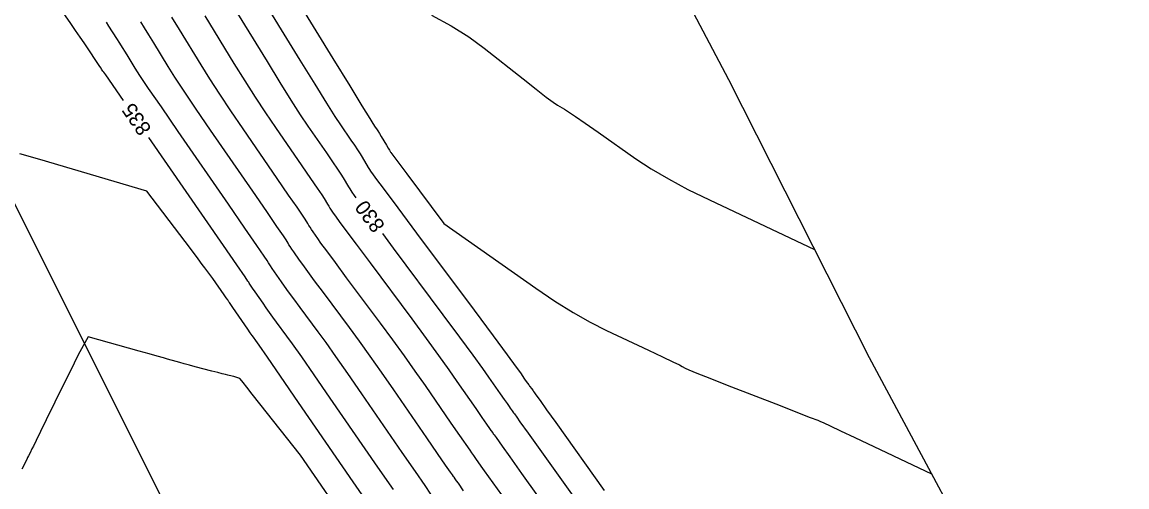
# Model space of a CAD drawing. Extents: x 1715724 to 1716561, y 394063 to 395906.
# Drawn here: x 1716345.4 to 1716449.4, y 394468.5 to 394512.3 of the extents above; entities that cross this region are included whole.
import ezdxf

# ---------------------------------------------------------------- set-up
doc = ezdxf.new("R2010")
doc.units = 0
for name, color, linetype in [('DT_X_Contour_Major', 7, 'Continuous'), ('DT_X_Contour_Minor', 7, 'Continuous'), ('DT_X_TIN_Hull', 7, 'Continuous'), ('GE_P_CL_10', 7, 'Continuous')]:
    doc.layers.add(name, color=color, linetype=linetype)

msp = doc.modelspace()

# ---------------------------------------------------------------- linework, layer by layer
at = {"layer": 'DT_X_Contour_Major'}
for points in [[(1716354.92, 394504.91), (1716353.24, 394507.35), (1716353.05, 394507.6), (1716353.01, 394507.66), (1716352.98, 394507.7), (1716352.92, 394507.79), (1716352.85, 394507.88), (1716352.8, 394507.97), (1716352.68, 394508.14), (1716352.5, 394508.41), (1716351.52, 394509.88), (1716351.21, 394510.34), (1716350.84, 394510.89), (1716350.4, 394511.53), (1716349.89, 394512.26), (1716347.37, 394515.88)], [(1716365, 394514.17), (1716368.43, 394508.58), (1716369.63, 394506.62), (1716370.68, 394504.96), (1716371.56, 394503.58), (1716372.29, 394502.5), (1716374.02, 394499.99), (1716374.6, 394499.14), (1716375.06, 394498.47), (1716375.39, 394497.97), (1716375.6, 394497.64), (1716376.11, 394496.8), (1716376.23, 394496.61), (1716376.33, 394496.44), (1716376.42, 394496.3), (1716376.65, 394495.97), (1716376.8, 394495.77)], [(1716380.33, 394468.27), (1716378.86, 394470.4), (1716374.39, 394476.89), (1716372.88, 394479.08), (1716371.7, 394480.78), (1716370.84, 394482), (1716370.31, 394482.73), (1716369.34, 394484.03), (1716368.99, 394484.51), (1716368.66, 394484.97), (1716368.35, 394485.4), (1716368.06, 394485.82), (1716367.32, 394486.9), (1716367.07, 394487.26), (1716366.88, 394487.53), (1716366.76, 394487.71), (1716366.71, 394487.8), (1716366.64, 394487.91), (1716366.36, 394488.31), (1716365.6, 394489.43), (1716364.34, 394491.26), (1716362.58, 394493.8), (1716357.31, 394501.45)], [(1716379.3, 394492.4), (1716380.32, 394491.02), (1716384.99, 394484.75), (1716386.57, 394482.62), (1716387.82, 394480.93), (1716388.73, 394479.68), (1716389.3, 394478.87), (1716390.39, 394477.3), (1716390.75, 394476.77), (1716391.03, 394476.37), (1716391.23, 394476.09), (1716391.34, 394475.94), (1716391.52, 394475.69), (1716391.59, 394475.6), (1716391.65, 394475.51), (1716391.72, 394475.42), (1716391.95, 394475.09), (1716392.25, 394474.66), (1716393.02, 394473.58), (1716394.27, 394471.83), (1716395.99, 394469.42), (1716402.94, 394459.7)]]:
    msp.add_lwpolyline(points, dxfattribs=at)
at = {"layer": 'DT_X_Contour_Minor'}
for points in [[(1716369.83, 394516.73), (1716374.63, 394508.88), (1716376.22, 394506.29), (1716377.37, 394504.41), (1716378.1, 394503.22), (1716378.4, 394502.75), (1716378.63, 394502.41), (1716378.73, 394502.26), (1716378.86, 394502.07), (1716379.01, 394501.82), (1716379.18, 394501.54), (1716379.68, 394500.71), (1716379.84, 394500.44), (1716379.96, 394500.24), (1716380.04, 394500.11), (1716380.07, 394500.07), (1716380.09, 394500.03), (1716380.19, 394499.9), (1716380.47, 394499.52), (1716380.94, 394498.89), (1716381.6, 394498.01), (1716385.08, 394493.33), (1716393.73, 394487.26), (1716395.53, 394486.03), (1716397.25, 394484.96), (1716398.87, 394484.04), (1716400.4, 394483.26), (1716404.36, 394481.4), (1716405.67, 394480.78), (1716406.63, 394480.32), (1716407.26, 394480.02), (1716407.53, 394479.88), (1716407.81, 394479.71), (1716408.14, 394479.56), (1716408.91, 394479.25), (1716410.12, 394478.77), (1716411.77, 394478.12), (1716416.75, 394476.18), (1716418.39, 394475.54), (1716419.58, 394475.08), (1716420.3, 394474.8), (1716420.56, 394474.7), (1716420.64, 394474.67), (1716420.86, 394474.56), (1716421.46, 394474.28), (1716422.44, 394473.82), (1716423.79, 394473.18), (1716431.01, 394469.76)], [(1716367.42, 394515.45), (1716371.53, 394508.73), (1716372.92, 394506.46), (1716374.02, 394504.68), (1716374.83, 394503.4), (1716375.35, 394502.62), (1716376.33, 394501.2), (1716376.67, 394500.7), (1716376.96, 394500.27), (1716377.2, 394499.9), (1716377.39, 394499.59), (1716377.97, 394498.62), (1716378.09, 394498.42), (1716378.18, 394498.28), (1716378.25, 394498.18), (1716378.37, 394498), (1716378.66, 394497.6), (1716379.45, 394496.54), (1716380.74, 394494.81), (1716382.52, 394492.42), (1716387.93, 394485.16), (1716389.72, 394482.75), (1716391.04, 394480.96), (1716391.9, 394479.8), (1716392.29, 394479.27), (1716392.69, 394478.68), (1716392.84, 394478.47), (1716392.96, 394478.29), (1716393.07, 394478.15), (1716393.15, 394478.03), (1716393.36, 394477.75), (1716393.43, 394477.66), (1716393.49, 394477.58), (1716393.53, 394477.52), (1716393.62, 394477.39), (1716393.76, 394477.19), (1716394.14, 394476.66), (1716394.76, 394475.79), (1716395.62, 394474.59), (1716400.19, 394468.2)], [(1716390.53, 394467.77), (1716388.91, 394470.03), (1716388.61, 394470.47), (1716388.1, 394471.21), (1716387.9, 394471.48), (1716387.71, 394471.75), (1716387.55, 394471.98), (1716386.58, 394473.37), (1716385.78, 394474.54), (1716383.34, 394478.08), (1716382.39, 394479.44), (1716381.37, 394480.87), (1716380.28, 394482.37), (1716379.12, 394483.94), (1716375.93, 394488.23), (1716374.87, 394489.66), (1716374.06, 394490.75), (1716373.51, 394491.5), (1716373.21, 394491.91), (1716372.78, 394492.54), (1716372.63, 394492.77), (1716372.49, 394492.98), (1716372.37, 394493.16), (1716372.27, 394493.33), (1716372.01, 394493.75), (1716371.78, 394494.11), (1716371.27, 394494.86), (1716370.47, 394496.02), (1716369.4, 394497.57), (1716366.18, 394502.25), (1716365.02, 394503.94), (1716363.98, 394505.51), (1716363.05, 394506.95), (1716362.22, 394508.27), (1716360.18, 394511.62), (1716359.48, 394512.76)], [(1716362.59, 394512.89), (1716365.32, 394508.42), (1716366.34, 394506.79), (1716367.33, 394505.24), (1716368.29, 394503.76), (1716369.23, 394502.38), (1716371.71, 394498.78), (1716372.54, 394497.58), (1716373.16, 394496.66), (1716373.59, 394496.04), (1716373.8, 394495.7), (1716374.12, 394495.17), (1716374.24, 394494.98), (1716374.36, 394494.79), (1716374.48, 394494.6), (1716374.6, 394494.42), (1716374.93, 394493.94), (1716375.23, 394493.54), (1716375.86, 394492.68), (1716376.82, 394491.38), (1716378.13, 394489.62), (1716382.06, 394484.35), (1716383.43, 394482.5), (1716384.59, 394480.9), (1716385.56, 394479.56), (1716386.32, 394478.47), (1716388.08, 394475.92), (1716388.67, 394475.07), (1716389.1, 394474.44), (1716389.39, 394474.03), (1716389.52, 394473.84), (1716389.68, 394473.63), (1716389.74, 394473.54), (1716389.82, 394473.44), (1716389.91, 394473.31), (1716390, 394473.17), (1716390.28, 394472.78), (1716390.58, 394472.35), (1716391.29, 394471.36), (1716392.4, 394469.8), (1716393.91, 394467.68)], [(1716383.93, 394512.96), (1716385.77, 394511.96), (1716387.42, 394510.92), (1716388.88, 394509.85), (1716392.54, 394506.95), (1716393.77, 394505.99), (1716394.71, 394505.25), (1716395.38, 394504.75), (1716395.77, 394504.49), (1716396.43, 394504.1), (1716396.82, 394503.86), (1716397.48, 394503.42), (1716398.4, 394502.78), (1716399.61, 394501.94), (1716403.17, 394499.44), (1716404.6, 394498.49), (1716406.24, 394497.53), (1716408.06, 394496.55), (1716410.09, 394495.56), (1716419.99, 394490.89)], [(1716383.87, 394467.86), (1716383.31, 394468.66), (1716382.41, 394469.97), (1716381.16, 394471.78), (1716377.37, 394477.28), (1716376.05, 394479.2), (1716374.92, 394480.81), (1716373.99, 394482.12), (1716373.25, 394483.13), (1716371.54, 394485.43), (1716370.95, 394486.23), (1716370.46, 394486.9), (1716370.07, 394487.44), (1716369.78, 394487.85), (1716369.14, 394488.78), (1716368.92, 394489.1), (1716368.75, 394489.34), (1716368.63, 394489.53), (1716368.56, 394489.64), (1716368.43, 394489.86), (1716368.17, 394490.25), (1716367.47, 394491.26), (1716366.34, 394492.9), (1716364.79, 394495.16), (1716360.06, 394502.01), (1716358.48, 394504.31), (1716357.28, 394506.06), (1716356.46, 394507.29), (1716356.02, 394507.97), (1716355.35, 394509.06), (1716355.09, 394509.48), (1716354.83, 394509.9), (1716354.56, 394510.33), (1716354.29, 394510.76), (1716353.55, 394511.93), (1716353.31, 394512.31)], [(1716386.93, 394468.16), (1716386.45, 394468.87), (1716386.28, 394469.11), (1716386.16, 394469.29), (1716386.06, 394469.43), (1716386, 394469.51), (1716385.89, 394469.66), (1716385.71, 394469.92), (1716385.24, 394470.59), (1716384.5, 394471.67), (1716383.47, 394473.16), (1716380.36, 394477.68), (1716379.22, 394479.32), (1716378.15, 394480.84), (1716377.13, 394482.25), (1716376.19, 394483.54), (1716373.74, 394486.83), (1716372.91, 394487.94), (1716372.26, 394488.82), (1716371.79, 394489.47), (1716371.5, 394489.88), (1716370.96, 394490.66), (1716370.77, 394490.93), (1716370.62, 394491.16), (1716370.5, 394491.34), (1716370.41, 394491.48), (1716370.22, 394491.8), (1716369.97, 394492.18), (1716369.37, 394493.06), (1716368.41, 394494.46), (1716367.1, 394496.37), (1716363.12, 394502.13), (1716361.75, 394504.12), (1716360.63, 394505.79), (1716359.75, 394507.12), (1716359.12, 394508.12), (1716357.76, 394510.34), (1716357.29, 394511.12), (1716356.88, 394511.78), (1716356.54, 394512.33)], [(1716378.24, 394466.57), (1716376.55, 394469.02), (1716371.41, 394476.49), (1716369.71, 394478.95), (1716368.47, 394480.75), (1716367.7, 394481.87), (1716367.38, 394482.32), (1716367.15, 394482.63), (1716367.03, 394482.79), (1716366.86, 394483.04), (1716366.63, 394483.37), (1716366.34, 394483.79), (1716365.49, 394485.02), (1716365.22, 394485.42), (1716365.02, 394485.71), (1716364.9, 394485.89), (1716364.85, 394485.95), (1716364.85, 394485.96), (1716364.73, 394486.14), (1716364.58, 394486.34), (1716364.39, 394486.63), (1716363.32, 394488.17), (1716362.58, 394489.17), (1716362.34, 394489.49), (1716361.95, 394490), (1716361.41, 394490.72), (1716360.72, 394491.63), (1716357.12, 394496.37), (1716347.05, 394499.35), (1716345.15, 394499.91)], [(1716376.5, 394464.37), (1716371.57, 394471.53), (1716367.76, 394476.35), (1716367.04, 394477.26), (1716366.52, 394477.93), (1716366.19, 394478.35), (1716366.05, 394478.52), (1716365.86, 394478.75), (1716365.58, 394478.84), (1716365.51, 394478.87), (1716365.41, 394478.89), (1716365.3, 394478.92), (1716365.15, 394478.96), (1716364.74, 394479.05), (1716364.53, 394479.1), (1716364.21, 394479.19), (1716363.79, 394479.3), (1716363.25, 394479.44), (1716361.68, 394479.85), (1716361.13, 394480), (1716360.64, 394480.13), (1716360.23, 394480.24), (1716359.89, 394480.33), (1716359.07, 394480.56), (1716358.67, 394480.67), (1716358.09, 394480.83), (1716357.33, 394481.05), (1716356.39, 394481.31), (1716351.59, 394482.65), (1716350.82, 394481.25), (1716350.6, 394480.83), (1716350.27, 394480.17), (1716349.82, 394479.28), (1716349.27, 394478.16), (1716347.65, 394474.84), (1716347.11, 394473.74), (1716346.7, 394472.91), (1716346.43, 394472.37), (1716346.3, 394472.1), (1716346.13, 394471.75), (1716345.98, 394471.46), (1716345.89, 394471.29), (1716345.8, 394471.1), (1716345.33, 394470.2)]]:
    msp.add_lwpolyline(points, dxfattribs=at)
at = {"layer": 'DT_X_TIN_Hull'}
msp.add_lwpolyline([(1716463.55, 394299.53), (1716471.86, 394306.26), (1716483.85, 394306.75), (1716504.79, 394314.54), (1716501.89, 394321.94), (1716496.82, 394331.94), (1716489.52, 394351.03), (1716488, 394358.9), (1716476.67, 394377.28), (1716464.97, 394402.5), (1716450.77, 394431.32), (1716438.69, 394455.43), (1716425.17, 394480.67), (1716411.91, 394506.87), (1716399.57, 394530.29)], dxfattribs=at)
at = {"layer": 'GE_P_CL_10'}
msp.add_line((1716447.81, 394289.08), (1716249.46, 394685.42), dxfattribs=at)

# ---------------------------------------------------------------- texts
at = {"layer": 'DT_X_Contour_Major'}
for s, rotation, p in [('835', 124.5933, (1716357.6, 394502.26)), ('830', 126.5546, (1716379.6, 394493.16))]:
    msp.add_text(s, height=1.4, rotation=rotation, dxfattribs=at).set_placement(p)

doc.saveas('drawing.dxf')
